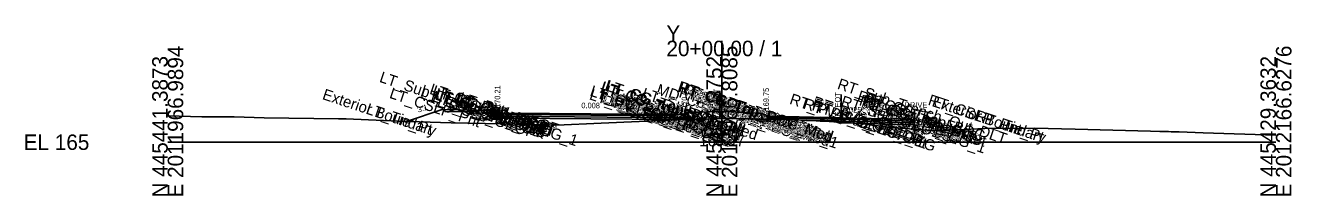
# Model space of a CAD drawing. Extents: x -26 to 3203, y -10 to 9532.
# Drawn here: x 974.3 to 1202.8, y 3990.3 to 4021.2 of the extents above; entities that cross this region are included whole.
import ezdxf

# ---------------------------------------------------------------- set-up
doc = ezdxf.new("R2010")
doc.units = 0
for name, color, linetype in [('Default', 7, 'Continuous'), ('Exist CMT Pavement', 7, 'Continuous'), ('Exist Cross Section Cell', 7, 'Continuous'), ('Exist XS Center Line Elevation Label', 7, 'Continuous'), ('Exist XS Ground Line', 7, 'Continuous'), ('Prop CMT Conc Surface', 7, 'Continuous'), ('Prop CMT Concrete Structures', 7, 'Continuous'), ('Prop CMT Pvmt Course 1', 7, 'Continuous'), ('Prop CMT Pvmt Course 1 CG', 7, 'Continuous'), ('Prop CMT Pvmt Course 2', 7, 'Continuous'), ('Prop CMT Pvmt Course 2 Wedge', 7, 'Continuous'), ('Prop CMT Pvmt Course 3', 7, 'Continuous'), ('Prop CMT Pvmt Course 3 Wedge', 7, 'Continuous'), ('Prop CMT Pvmt Surface', 7, 'Continuous'), ('Prop CMT Shear Line', 7, 'Continuous'), ('Prop CMT Shear Line Text', 7, 'Continuous'), ('Prop CMT Slope Grass', 7, 'Continuous'), ('Prop CMT Subgrade Earthwork', 7, 'Continuous'), ('Prop XS Hydro Elevations', 7, 'Continuous'), ('Prop XS Label Text', 7, 'Continuous'), ('Prop XS SE Text', 7, 'Continuous'), ('Prop XS Side Slope Text', 7, 'Continuous'), ('Scratch_Level_0', 7, 'Continuous')]:
    doc.layers.add(name, color=color, linetype=linetype)

msp = doc.modelspace()

# ---------------------------------------------------------------- linework, layer by layer
at = {"layer": 'Exist CMT Pavement'}
msp.add_lwpolyline([(1108.75, 4004.18), (1110.29, 4004.18), (1110.6, 4004.18), (1112.12, 4004.11), (1112.72, 4004.08), (1113.21, 4004.06), (1115.22, 4003.95), (1117.01, 4003.87), (1117.72, 4003.83), (1118.51, 4003.78), (1120.24, 4003.68), (1121.14, 4003.64), (1121.51, 4003.62), (1121.96, 4003.59), (1122.74, 4003.54), (1124.07, 4003.43), (1125.18, 4003.33), (1125.9, 4003.24), (1126.71, 4003.16)], dxfattribs=at)
at = {"layer": 'Exist Cross Section Cell'}
for p, q in [((1100, 4000), (1100, 4018.37)), ((1000, 4000), (1100, 4000)), ((1100, 4000), (1200, 4000))]:
    msp.add_line(p, q, dxfattribs=at)
at = {"layer": 'Exist XS Ground Line'}
msp.add_lwpolyline([(1000, 4004.78), (1006.16, 4004.57), (1011.97, 4004.57), (1017.41, 4004.44), (1030.85, 4004.23), (1031.58, 4004.22), (1032.22, 4004.21), (1041.67, 4003.81), (1051.13, 4003.53), (1060.38, 4003.34), (1060.74, 4003.33), (1070.24, 4003.1), (1078.25, 4003.44), (1090.55, 4003.98), (1094.61, 4004.12), (1096.08, 4004.16), (1099.63, 4004.27), (1100.25, 4004.27), (1102.72, 4004.25), (1105.35, 4004.23), (1107.74, 4004.19), (1108.05, 4004.19), (1110.29, 4004.18), (1110.6, 4004.18), (1112.12, 4004.11), (1112.72, 4004.08), (1113.21, 4004.06), (1115.22, 4003.95), (1117.01, 4003.87), (1117.72, 4003.83), (1118.51, 4003.78), (1120.24, 4003.68), (1121.14, 4003.64), (1121.51, 4003.62), (1121.96, 4003.59), (1122.74, 4003.54), (1124.07, 4003.43), (1125.18, 4003.33), (1125.9, 4003.24), (1126.71, 4003.16), (1130.69, 4002.69), (1138.66, 4002.04), (1147.49, 4002.47), (1156.44, 4002.53), (1163.77, 4002.36), (1177.36, 4002), (1179.05, 4001.96), (1180.06, 4001.93), (1180.59, 4001.91), (1181.11, 4001.89), (1182.56, 4001.88), (1186.85, 4001.72), (1200, 4001.27)], dxfattribs=at)
at = {"layer": 'Prop CMT Conc Surface'}
for points in [[(1055.01, 4005.8), (1050.01, 4005.9)], [(1059.51, 4005.21), (1059.51, 4005.71), (1059.01, 4005.71)], [(1061.51, 4005.27), (1059.51, 4005.21)], [(1091.25, 4005.02), (1093.25, 4005.01), (1093.25, 4005.18), (1094, 4005.43)], [(1108.75, 4004.73), (1108, 4004.75), (1108, 4004.92), (1107.24, 4005.17)]]:
    msp.add_lwpolyline(points, dxfattribs=at)
at = {"layer": 'Prop CMT Concrete Structures'}
for points in [[(1050.01, 4005.57), (1050.01, 4005.9)], [(1050.01, 4005.9), (1055.01, 4005.8)], [(1055.01, 4005.47), (1050.01, 4005.57)], [(1055.01, 4005.8), (1055.01, 4005.47)], [(1061.51, 4005.27), (1059.51, 4005.21), (1059.51, 4005.71), (1059.01, 4005.71)], [(1059.01, 4005.71), (1059.01, 4004.71), (1061.51, 4004.69)], [(1061.51, 4004.69), (1061.51, 4005.27)], [(1091.25, 4005.02), (1093.25, 4005.01), (1093.25, 4005.18), (1094, 4005.43)], [(1091.25, 4004.44), (1091.25, 4005.02)], [(1094, 4004.42), (1091.25, 4004.44)], [(1094, 4005.43), (1094, 4004.42)], [(1108.75, 4004.73), (1108, 4004.75), (1108, 4004.92), (1107.24, 4005.17)], [(1107.24, 4005.17), (1107.24, 4004.19)], [(1107.24, 4004.19), (1108.75, 4004.15)], [(1108.75, 4004.15), (1108.75, 4004.73)], [(1134.75, 4003.5), (1134.75, 4004.08)]]:
    msp.add_lwpolyline(points, dxfattribs=at)
at = {"layer": 'Prop CMT Pvmt Course 1'}
for points in [[(1091.25, 4005.02), (1061.51, 4005.27)], [(1061.51, 4005.27), (1061.51, 4005.02)], [(1061.51, 4005.02), (1091.25, 4004.77)], [(1091.25, 4004.77), (1091.25, 4005.02)], [(1091.25, 4004.77), (1091.25, 4004.77)], [(1108.75, 4004.73), (1134.75, 4004.08)], [(1108.75, 4004.48), (1108.75, 4004.73)], [(1134.75, 4003.83), (1126.71, 4004.03), (1108.75, 4004.48)], [(1108.75, 4004.48), (1108.75, 4004.48)], [(1134.75, 4004.08), (1134.75, 4003.83)]]:
    msp.add_lwpolyline(points, dxfattribs=at)
at = {"layer": 'Prop CMT Pvmt Course 1 CG'}
for points in [[(1061.51, 4004.69), (1058.51, 4004.71), (1058.18, 4004.38)], [(1058.18, 4004.38), (1061.51, 4004.36)], [(1061.51, 4004.36), (1061.51, 4004.69)], [(1091.25, 4004.44), (1094.5, 4004.41), (1094.84, 4004.08)], [(1091.25, 4004.11), (1091.25, 4004.44)], [(1094.84, 4004.08), (1091.25, 4004.11)], [(1108.75, 4004.15), (1106.74, 4004.2), (1106.41, 4003.88)], [(1108.75, 4003.82), (1108.75, 4004.15)], [(1106.41, 4003.88), (1108.75, 4003.82)], [(1134.75, 4003.17), (1134.75, 4003.5)]]:
    msp.add_lwpolyline(points, dxfattribs=at)
at = {"layer": 'Prop CMT Pvmt Course 2'}
for points in [[(1091.25, 4004.77), (1061.51, 4005.02)], [(1061.51, 4005.02), (1061.51, 4004.69)], [(1061.51, 4004.69), (1091.25, 4004.44)], [(1091.25, 4004.77), (1091.25, 4004.77)], [(1108.75, 4004.48), (1108.75, 4004.48)], [(1121.51, 4003.83), (1121.51, 4004.16)], [(1121.51, 4004.16), (1134.75, 4003.83)], [(1134.75, 4003.5), (1121.51, 4003.83)], [(1134.75, 4003.83), (1134.75, 4003.5)]]:
    msp.add_lwpolyline(points, dxfattribs=at)
for points in [[(1091.25, 4004.77), (1091.25, 4004.44), (1091.25, 4004.44)], [(1108.75, 4004.48), (1108.75, 4004.15), (1108.75, 4004.15)]]:
    msp.add_lwpolyline(points, close=True, dxfattribs=at)
at = {"layer": 'Prop CMT Pvmt Course 2 Wedge'}
for points in [[(1090.55, 4004.78), (1091.25, 4004.77)], [(1091.25, 4004.77), (1091.25, 4004.44)], [(1108.75, 4004.18), (1108.75, 4004.48)], [(1108.75, 4004.48), (1110.29, 4004.44), (1110.6, 4004.44), (1112.12, 4004.4), (1112.72, 4004.38), (1113.21, 4004.37), (1115.22, 4004.32), (1117.01, 4004.28), (1117.72, 4004.26), (1118.51, 4004.24), (1120.24, 4004.2), (1121.14, 4004.17), (1121.51, 4004.16)], [(1121.51, 4003.83), (1121.14, 4003.84), (1120.24, 4003.86), (1118.51, 4003.91), (1117.72, 4003.93), (1117.01, 4003.94), (1115.22, 4003.99), (1113.88, 4004.02), (1113.21, 4004.06), (1112.72, 4004.08), (1112.12, 4004.11), (1110.6, 4004.18), (1110.29, 4004.18), (1108.75, 4004.18)], [(1121.51, 4004.16), (1121.51, 4003.83)]]:
    msp.add_lwpolyline(points, dxfattribs=at)
at = {"layer": 'Prop CMT Pvmt Course 3'}
for points in [[(1091.25, 4004.44), (1061.51, 4004.69)], [(1061.51, 4004.69), (1061.51, 4004.36)], [(1061.51, 4004.36), (1091.25, 4004.11)], [(1091.25, 4004.44), (1091.25, 4004.44), (1091.25, 4004.11), (1091.25, 4004.11)], [(1091.25, 4004.11), (1091.25, 4004.44)], [(1108.75, 4004.15), (1108.75, 4004.15), (1108.75, 4003.82), (1108.75, 4003.82)], [(1108.75, 4003.82), (1108.75, 4004.15)], [(1121.51, 4003.83), (1134.75, 4003.5)], [(1121.51, 4003.5), (1121.51, 4003.83)], [(1134.75, 4003.17), (1121.51, 4003.5)], [(1134.75, 4003.5), (1134.75, 4003.17)]]:
    msp.add_lwpolyline(points, dxfattribs=at)
at = {"layer": 'Prop CMT Pvmt Course 3 Wedge'}
for points in [[(1091.25, 4004.44), (1091.25, 4004.11)], [(1126.71, 4003.16), (1125.9, 4003.24), (1125.18, 4003.33), (1124.07, 4003.43), (1122.74, 4003.54), (1121.96, 4003.59), (1121.51, 4003.62), (1121.14, 4003.64), (1120.24, 4003.68), (1118.51, 4003.78), (1117.72, 4003.83), (1117.01, 4003.87), (1115.22, 4003.95), (1113.88, 4004.02)], [(1113.88, 4004.02), (1115.22, 4003.99)], [(1115.22, 4003.99), (1117.01, 4003.94), (1117.72, 4003.93), (1118.51, 4003.91), (1120.24, 4003.86), (1121.14, 4003.84), (1121.51, 4003.83)], [(1121.51, 4003.83), (1121.51, 4003.5)]]:
    msp.add_lwpolyline(points, dxfattribs=at)
at = {"layer": 'Prop CMT Pvmt Surface'}
for points in [[(1091.25, 4005.02), (1061.51, 4005.27)], [(1108.75, 4004.73), (1134.75, 4004.08)]]:
    msp.add_lwpolyline(points, dxfattribs=at)
at = {"layer": 'Prop CMT Shear Line'}
msp.add_line((1134.75, 4001.45), (1134.75, 4006.03), dxfattribs=at)
at = {"layer": 'Prop CMT Slope Grass'}
for points in [[(1049.51, 4005.9), (1043.12, 4003.77)], [(1059.01, 4005.71), (1049.51, 4005.9)], [(1094, 4005.43), (1100.62, 4005.56)], [(1107.24, 4005.17), (1100.62, 4005.56)]]:
    msp.add_lwpolyline(points, dxfattribs=at)
at = {"layer": 'Prop CMT Subgrade Earthwork'}
msp.add_line((1121.51, 4003.5), (1121.5, 4003.62), dxfattribs=at)
for points in [[(1061.51, 4004.36), (1058.18, 4004.38), (1056.81, 4005.75)], [(1091.25, 4004.11), (1061.51, 4004.36)], [(1061.51, 4004.36), (1061.51, 4004.36)], [(1094.84, 4004.08), (1091.25, 4004.11)], [(1091.25, 4004.11), (1091.25, 4004.11)], [(1091.25, 4004.11), (1091.25, 4004.11)], [(1096.23, 4005.47), (1094.84, 4004.08)], [(1104.99, 4005.3), (1106.41, 4003.88)], [(1108.75, 4003.82), (1108.73, 4004.18)], [(1106.41, 4003.88), (1108.75, 4003.82)], [(1108.75, 4003.82), (1108.75, 4003.82)], [(1108.75, 4003.82), (1108.75, 4003.82)], [(1121.51, 4003.5), (1134.75, 4003.17)], [(1134.75, 4003.17), (1134.75, 4003.17)]]:
    msp.add_lwpolyline(points, dxfattribs=at)
at = {"layer": 'Prop XS Label Text'}
for p, q in [((1099.63, 4009.27), (1099.63, 4004.27)), ((1121.51, 4008.62), (1121.51, 4003.62))]:
    msp.add_line(p, q, dxfattribs=at)

# ---------------------------------------------------------------- texts
at = {"layer": 'Default'}
msp.add_text('-', height=0.0001, dxfattribs=at).set_placement((1000, 4000))
at = {"layer": 'Exist Cross Section Cell'}
for s, p in [('Y', (1090, 4018.37)), ('20+00.00 / 1', (1090, 4015.57)), ('EL 165', (974, 3998.6))]:
    msp.add_text(s, height=2.8, dxfattribs=at).set_placement(p)
for s, p in [('N 445441.3873', (1000, 3990)), ('E 2011966.9894', (1002.8, 3990)), ('N 445435.3752', (1100, 3990)), ('E 2012066.8085', (1102.8, 3990)), ('N 445429.3632', (1200, 3990)), ('E 2012166.6276', (1202.8, 3990))]:
    msp.add_text(s, height=2.8, rotation=90, dxfattribs=at).set_placement(p)
at = {"layer": 'Exist XS Center Line Elevation Label'}
msp.add_text('169.27', height=2, dxfattribs=at).set_placement((1095.94, 3999.27))
at = {"layer": 'Prop CMT Shear Line Text'}
msp.add_text('DRIVE', height=1, rotation=360, dxfattribs=at).set_placement((1132.99, 4006.24))
at = {"layer": 'Prop XS Hydro Elevations'}
for s, p in [('170.21', (1060.01, 4006.21)), ('170.01', (1093.75, 4006.01)), ('169.75', (1108.5, 4005.75))]:
    msp.add_text(s, height=1, rotation=90, dxfattribs=at).set_placement(p)
at = {"layer": 'Prop XS Label Text'}
for p in [(1099.53, 4005.3), (1121.41, 4004.65)]:
    msp.add_text('E. EOT', height=1, rotation=90, dxfattribs=at).set_placement(p)
at = {"layer": 'Prop XS SE Text'}
for s, rotation, p in [('0.008', 359.5232, (1074.65, 4006.16)), ('0.025', 358.5679, (1121.84, 4005.42))]:
    msp.add_text(s, height=1, rotation=rotation, dxfattribs=at).set_placement(p)
at = {"layer": 'Prop XS Side Slope Text'}
msp.add_text('3:1', height=1, rotation=18.4349, dxfattribs=at).set_placement((1045.25, 4005.35))
at = {"layer": 'Scratch_Level_0'}
for s, p in [('LT_Sub_Trench_Out_DLT', (1038.06, 4010.95)), ('LT_CG_Top Gut Out', (1077.9, 4009.07)), ('LT_CG_Top FOC Out', (1078.02, 4009.2)), ('LT_CG_Top BOC Out', (1078.73, 4009.46)), ('LT_CG_Top_BOC_Med', (1078.88, 4009.41)), ('RT_CG_Top_Face_Med', (1091.86, 4009.24)), ('RT_CG_Top_BOC_Med', (1092.07, 4009.17)), ('RT_Sub_Trench_Out_DLT', (1120.71, 4009.71)), ('Exterior Boundary', (1027.76, 4007.83)), ('LT_CSLP_Pnt', (1039.87, 4008.06)), ('LT_CG1_Shelf_Out', (1045.44, 4008.02)), ('LT_CG_Top_Face', (1047.11, 4008.79)), ('LT_CG_Top_BOC', (1047.58, 4008.47)), ('LT_CG_Bot_BOC', (1047.61, 4007.46)), ('LT_CG_Top_Gut', (1048.04, 4007.98)), ('LT_Sub_OEOT_CG_1', (1048.12, 4007.76)), ('LT_CG_Bot_IE', (1051.63, 4006.93)), ('LT_PV2_OEOT', (1051.87, 4007.18)), ('LT_PV3_OEOT', (1051.87, 4006.85)), ('LT_PV1_OEOT', (1052.41, 4007.25)), ('LT_PV_Sub_Tie_Out', (1075.95, 4007.79)), ('LT_CG_Bot FOG Out', (1076.05, 4008.45)), ('LT_CG_Bot_IE_Med', (1077.71, 4007.9)), ('LT_PV_Sub_Tie_In', (1078.19, 4007.29)), ('LT_PV_OEEOP_EG', (1078.41, 4006.97)), ('LT_Sub_IEOT_CG_1', (1078.47, 4007.31)), ('LT_CG_Bot BOC Out', (1078.76, 4008.45)), ('LT_PV_IEEOP_EG', (1079.73, 4006.78)), ('LT_PV2_OEEOP', (1080.08, 4007.21)), ('LT_PV3_OEEOP', (1080.08, 4006.88)), ('LT_PV2_IEEOP', (1081.4, 4007)), ('LT_PV3_IEEOP', (1081.4, 4006.67)), ('LT_CG1_Shelf_In', (1082.96, 4007.21)), ('LT_PV1_PGL', (1083.14, 4006.68)), ('LT_Sub_DLT_In', (1085.42, 4008.02)), ('MD_Crown Point', (1088.04, 4008.7)), ('RT_CG_Bot_BOC_Med', (1092.1, 4008.18)), ('RT_CG_Top_Gut_Med', (1092.79, 4008.77)), ('RT_Sub_DLT_In', (1094.14, 4007.86)), ('RT_CG1_Shelf_In', (1095.16, 4007.01)), ('RT_CG_Bot_IE_Med', (1095.17, 4007.62)), ('RT_PV_Sub_Tie_In', (1095.63, 4007.5)), ('RT_Sub_IEOT_CG_1', (1095.93, 4007.04)), ('RT_PV_IEEOP_EG', (1097.18, 4006.99)), ('RT_PV2_IEEOP', (1098.86, 4006.73)), ('RT_PV_Sub_Tie_Out', (1112.08, 4006.98)), ('RT_CG_Top_Face', (1124.3, 4007.55)), ('RT_CG1_Shelf_Out', (1124.63, 4006.74)), ('RT_CG_Top_Gut', (1125.23, 4006.74)), ('RT_CG_Top_BOC', (1125.77, 4007.22)), ('RT_CSLP_Pnt', (1137.07, 4006.82)), ('LT_Tie_Pt', (1035.63, 4005.21)), ('LT_Sub_OEOP', (1048.48, 4006.56)), ('LT_Sub_OEOT', (1051.79, 4006.54)), ('LT_Sub_OEEOP', (1080, 4006.58)), ('LT_Sub_IEEOP', (1081.31, 4006.37)), ('LT_Sub_PGL', (1082.51, 4005.97)), ('LT_PV2_PGL', (1082.6, 4006.61)), ('LT_PV3_PGL', (1082.6, 4006.27)), ('LT_Sub_IEOP', (1085.75, 4006.05)), ('RT_Sub_IEOP', (1097.28, 4005.86)), ('RT_Sub_IEEOP', (1098.77, 4006.09)), ('RT_PV3_IEEOP', (1098.86, 4006.39)), ('RT_Sub_PGL', (1099.96, 4005.69)), ('RT_PV2_PGL', (1100.05, 4006.33)), ('RT_PV3_PGL', (1100.05, 4006)), ('RT_PV1_PGL', (1100.59, 4006.4)), ('RT_PV_OEEOP_EG', (1114.53, 4006.16)), ('RT_Sub_OEEOP', (1116.12, 4005.85)), ('RT_PV2_OEEOP', (1116.21, 4006.48)), ('RT_PV3_OEEOP', (1116.21, 4006.15)), ('RT_Sub_OEOT_CG_1', (1121.32, 4006.59)), ('RT_CG_Bot_IE', (1124.82, 4005.76)), ('RT_Sub_OEOT', (1124.98, 4005.37)), ('RT_PV2_OEOT', (1125.07, 4006.01)), ('RT_PV3_OEOT', (1125.07, 4005.67)), ('RT_PV1_OEOT', (1125.6, 4006.08)), ('RT_CG_Bot_BOC', (1125.8, 4006.2)), ('RT_Sub_OEOP', (1128.35, 4005.28)), ('Exterior Boundary', (1137.78, 4006.58)), ('RT_Tie_Pt', (1145.61, 4003.97))]:
    msp.add_text(s, height=2, rotation=341.5651, dxfattribs=at).set_placement(p)

doc.saveas('drawing.dxf')
